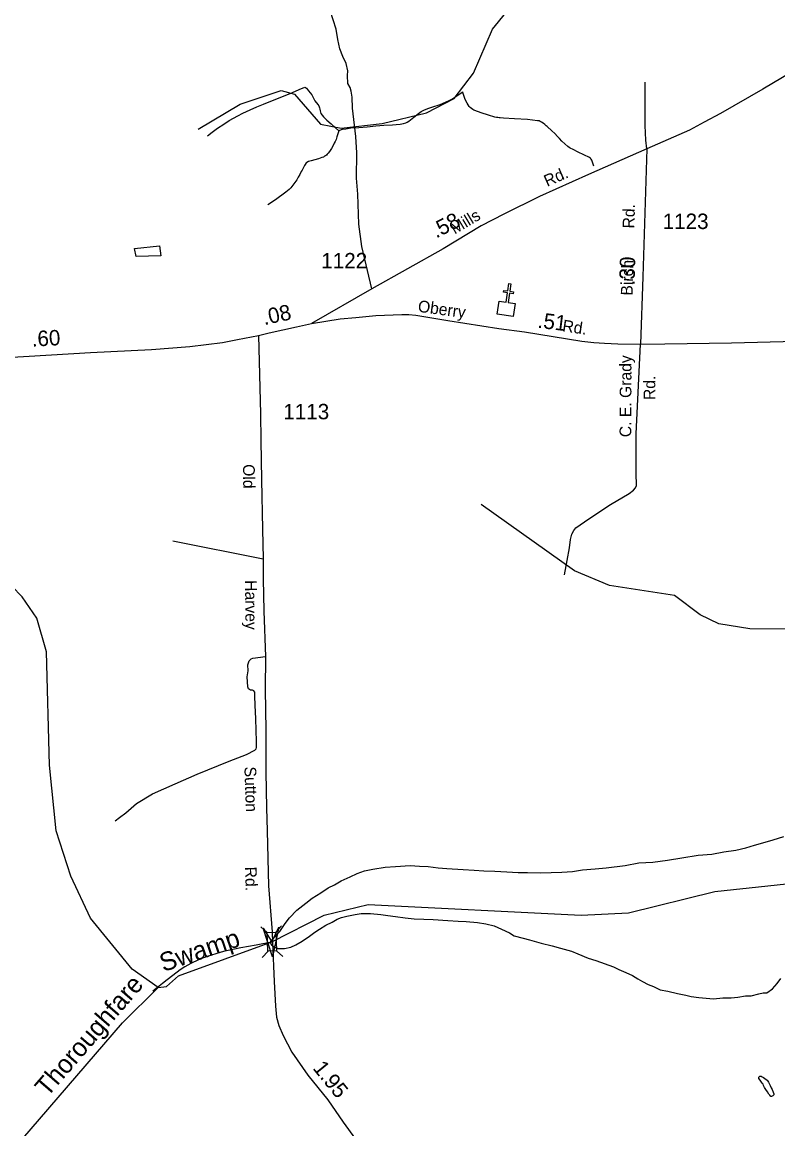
# Model space of a CAD drawing. Extents: x 2206922 to 2357709, y 510027 to 673830.
# Drawn here: x 2251460 to 2257580, y 541278 to 550239 of the extents above; entities that cross this region are included whole.
import ezdxf

# ---------------------------------------------------------------- set-up
doc = ezdxf.new("R2010")
doc.units = 0
for name, color, linetype in [('Exist Cultural Church CELL', 7, 'Continuous'), ('Exist Hydrographic Creek Single Shore', 7, 'Continuous'), ('Exist Hydrographic Creek Single Shore Label', 7, 'Continuous'), ('Exist Hydrographic Misc Water Feature', 7, 'Continuous'), ('Exist Road Non-System Type 51', 7, 'Continuous'), ('Exist Road Non-System Type 51 Label', 7, 'Continuous'), ('Exist Road Secondary Mileage Hundredths English Label', 7, 'Continuous'), ('Exist Road Secondary Structure Standard Bridge Attributed CELL', 7, 'Continuous'), ('Exist Road Secondary Structure Standard Bridge CELL', 7, 'Continuous'), ('Exist Road Secondary Type 51 Attributed', 7, 'Continuous'), ('Exist Road Secondary Type 51 Label', 7, 'Continuous'), ('Exist Road Secondary Type 51 Number Label', 7, 'Continuous')]:
    doc.layers.add(name, color=color, linetype=linetype)

msp = doc.modelspace()

# ---------------------------------------------------------------- linework, layer by layer
at = {"layer": 'Exist Cultural Church CELL'}
msp.add_lwpolyline([(2255322.1, 547979.6), (2255378.5, 547971.4), (2255389.6, 548046.7), (2255358, 548051.4), (2255360.3, 548067.2), (2255392, 548062.5), (2255400.8, 548122), (2255416.6, 548119.7), (2255407.8, 548060.2), (2255439.5, 548055.5), (2255437.1, 548039.7), (2255405.5, 548044.4), (2255394.3, 547969.1), (2255451.3, 547960.5), (2255435.7, 547855.2), (2255306.5, 547874.3)], close=True, dxfattribs=at)
at = {"layer": 'Exist Hydrographic Creek Single Shore'}
for points in [[(2252560.5, 542421.7), (2252627.5, 542430.2), (2252726.6, 542516.7), (2253480.8, 542793.8), (2253905.6, 543007.9), (2254262.6, 543095.7), (2255987.5, 543008.5), (2256370.6, 543027), (2257068.6, 543199.9), (2257851.7, 543282.5), (2258350.6, 543403.7), (2259471.6, 543820.5), (2260408.7, 544211.6)], [(2251380.6, 541104), (2252271.6, 542135.6), (2252560.5, 542421.7)]]:
    msp.add_lwpolyline(points, dxfattribs=at)
at = {"layer": 'Exist Hydrographic Misc Water Feature'}
for points in [[(2252885.5, 549371.4), (2253225.5, 549574.4), (2253557.5, 549685.8), (2253666.5, 549654.2), (2253876.5, 549413.8), (2254043.4, 549380.8), (2254376.4, 549416.8), (2254733.4, 549504.7), (2254957.6, 549621.5), (2255114.6, 549825), (2255269.4, 550182.6), (2255459.5, 550418.2)], [(2252959.5, 549316.8), (2252997.3, 549346.8), (2253043, 549379.2), (2253093, 549413.8), (2253136.5, 549442.2), (2253170.3, 549462.2), (2253206.2, 549480.7), (2253246.2, 549501.1), (2253305.7, 549529.4), (2253359.4, 549553.7), (2253413.3, 549574), (2253473.2, 549598.6), (2253562.8, 549633.4), (2253650.3, 549670), (2253704.3, 549692.3), (2253748.2, 549712.9), (2253754.1, 549710.8), (2253762.1, 549705.1), (2253778.5, 549683.2), (2253804.5, 549651.2), (2253831.2, 549601.8), (2253853.3, 549571.7), (2253861.1, 549560), (2253867.3, 549546.1), (2253871.8, 549534), (2253873.2, 549520.1), (2253879.8, 549498), (2253889.8, 549484.3), (2253900.1, 549472.2), (2253926.3, 549446.3), (2253962.2, 549416.6), (2253998.3, 549383.2), (2254024.8, 549357.3)], [(2254024.8, 549357.3), (2254033, 549363.4), (2254045.1, 549369.6), (2254054.7, 549371.4), (2254081, 549375.6), (2254120.7, 549382.2), (2254186.4, 549386.5), (2254254.4, 549391.2), (2254324.1, 549399.7), (2254390, 549404.5), (2254458.5, 549406.7), (2254488.2, 549409.1), (2254522, 549413.3), (2254548.3, 549417.5), (2254566.1, 549423.7), (2254578, 549428), (2254591.9, 549438.1), (2254605.5, 549448.2), (2254631.5, 549468.2), (2254669.3, 549498.6), (2254691, 549514.8), (2254712.9, 549526.9), (2254745.3, 549539), (2254776.7, 549551.3), (2254844.6, 549571.9), (2254886.8, 549590.3), (2254918.2, 549604.6), (2254944.2, 549618.5), (2254983.8, 549645), (2255027.7, 549675.3)], [(2256090.3, 549072.3), (2256075.9, 549114.2), (2256071.8, 549120.1), (2256067.5, 549128), (2256063.6, 549134.3), (2256061.6, 549138.2), (2256055.4, 549142), (2255963.1, 549185.1), (2255920.9, 549206.9), (2255896.9, 549218.6), (2255888.9, 549224.7), (2255878.9, 549232.7), (2255830.5, 549274), (2255810.8, 549296.1), (2255794.2, 549314), (2255772.2, 549337.6), (2255748.2, 549359.4), (2255711.7, 549392.9), (2255703.3, 549399.1), (2255691.2, 549411), (2255679.3, 549420.9), (2255665.4, 549428.7), (2255655.3, 549434.7), (2255645.3, 549438.6), (2255633.4, 549440.4), (2255551.6, 549449.9), (2255447.4, 549457.1), (2255357.2, 549462.2), (2255331.2, 549464.1), (2255321.5, 549463.9), (2255311.1, 549465.9), (2255301.2, 549467.8), (2255287.1, 549469.5), (2255271.5, 549475.5), (2255253.4, 549479.5), (2255227, 549487.1), (2255185.2, 549500.7), (2255118.7, 549526.1), (2255108.7, 549532.1), (2255099, 549540), (2255089, 549548), (2255080.8, 549555.8), (2255064.6, 549583.8), (2255048.4, 549613.4), (2255035.9, 549643.6), (2255029.5, 549669.3), (2255027.7, 549675.3)], [(2254024.8, 549357.3), (2254016.8, 549333.4), (2254009, 549309.4), (2254001.6, 549287.4), (2253995.2, 549273), (2253987.9, 549259.1), (2253977.8, 549239.1), (2253963.9, 549216.8), (2253948.1, 549190.8), (2253938.4, 549178.5), (2253930.2, 549170.8), (2253924.7, 549162.7), (2253916.5, 549156.7), (2253908.5, 549152.6), (2253900.3, 549146.6), (2253887, 549142.5), (2253860.5, 549132.3), (2253830.6, 549123.8), (2253799.2, 549115.6), (2253778.9, 549109.3), (2253764.8, 549101.3), (2253761.1, 549099.4), (2253751, 549087.1), (2253745.5, 549079.1), (2253739.3, 549062.9), (2253727.7, 549041.2), (2253719.7, 549029), (2253707.6, 549004.9), (2253696.1, 548984.7), (2253684, 548962.6), (2253666.8, 548940.5), (2253652.8, 548918.7), (2253634.6, 548898.3), (2253621.2, 548884.1), (2253595, 548862.1), (2253511.7, 548801.2), (2253449.8, 548759.1)], [(2252369.6, 548406.1), (2252571, 548428.1), (2252582, 548346.1), (2252382.1, 548340.6), (2252369.6, 548406.1)], [(2260408.7, 544211.6), (2260249.5, 544359.1), (2259996.7, 544682.3), (2259871.6, 544757), (2259620.6, 544853.9), (2259478.5, 544951.9), (2259201.5, 545216.6), (2258975.6, 545349), (2258658.5, 545404.6), (2257801.6, 545323.5), (2257351.5, 545326), (2257101.6, 545367.1), (2256950.7, 545439), (2256741.5, 545597.4), (2256215.5, 545676.9), (2255931.6, 545797.4), (2255177.6, 546334.1)], [(2252560.5, 542421.7), (2252351.5, 542570.2), (2252014.4, 542983.7), (2251854.5, 543324.7), (2251734.5, 543691.2), (2251680.6, 544223.6), (2251656.4, 545139.1), (2251578.5, 545412.9), (2251460.6, 545585.8), (2251292.5, 545759.7), (2250449.5, 546062.1), (2250157.5, 546110.6), (2249774.5, 546072.4), (2249600.6, 546013.6), (2248098.6, 545269.9)], [(2253468.3, 542786.8), (2253504.4, 542829.2), (2253546, 542877.3), (2253589.2, 542941.7), (2253624.7, 542987.9), (2253684.4, 543050.2), (2253758, 543106.8), (2253809.5, 543145.3), (2253879, 543190), (2253938.9, 543228.4), (2253988.3, 543254.6), (2254044.5, 543285.1), (2254116, 543317.7), (2254171.8, 543346.2), (2254233.5, 543366.9), (2254299.3, 543381.3), (2254399, 543395.9), (2254483.1, 543402.7), (2254603.2, 543409.7), (2254677, 543406.3), (2254748.8, 543402.7), (2254828.8, 543391.5), (2254898.9, 543386.2), (2255031, 543379.3), (2255119.1, 543373.7), (2255199.1, 543366.5), (2255287.1, 543365.4), (2255385.1, 543359.9), (2255477.4, 543355), (2255552.8, 543353.3), (2255654.5, 543352.1), (2255742.7, 543353.1), (2255830.7, 543355.6), (2255916.4, 543362.5), (2255996.8, 543374.8), (2256100.3, 543383.9), (2256188.3, 543392.5), (2256342.1, 543411.6), (2256454, 543430.8), (2256567.8, 543437.5), (2256685.5, 543452.6), (2256801.2, 543473.3), (2256933, 543494.4), (2257044.8, 543501.5), (2257142.6, 543520.4), (2257238.6, 543535.1), (2257320.4, 543553.6), (2257390.1, 543576.4), (2257475.8, 543598.7), (2257541.8, 543617.5), (2257627.3, 543644)], [(2253468.3, 542786.8), (2253478.7, 542767), (2253501.1, 542751), (2253531, 542739.2), (2253551.1, 542737.4), (2253583.1, 542737.9), (2253636.8, 542750), (2253676.6, 542768.4), (2253726.4, 542797), (2253786.3, 542837.4), (2253829.8, 542869.8), (2253867.3, 542896.2), (2253919.6, 542928.4), (2253971.3, 542952.6), (2254011, 542975), (2254046.5, 542989.1), (2254088.7, 542999.8), (2254156.2, 543014.4), (2254206.4, 543022.6), (2254280.5, 543023.2), (2254364.3, 543013.9), (2254422.2, 543006.3), (2254482.2, 542996.9), (2254560.2, 542985.5), (2254634.6, 542978.3), (2254712.3, 542976.8), (2254788.6, 542973.4), (2254908.1, 542966.3), (2254990.2, 542959.2), (2255056.2, 542957.4), (2255148.3, 542948.3), (2255214.7, 542938.8), (2255282.4, 542921.3), (2255342.8, 542893.9), (2255405, 542864.2), (2255443.1, 542840.6), (2255517.3, 542821.4), (2255569, 542807.9), (2255663.5, 542782.7), (2255751.3, 542759.3), (2255819.8, 542741.7), (2255909.6, 542716.8), (2255960.1, 542695), (2256042.1, 542659.9), (2256106.5, 542640.1), (2256248.8, 542591.4), (2256290.8, 542567.7), (2256348.8, 542544.3), (2256403.4, 542518.7), (2256445.4, 542492.9), (2256483.3, 542471.3), (2256530.1, 542447.7), (2256571.7, 542430.1), (2256626.1, 542404.4), (2256688, 542393.1), (2256766.3, 542373.5), (2256834.4, 542360.5), (2256878.3, 542350.6), (2256938.2, 542341.1), (2257000.1, 542337.5), (2257058.3, 542332), (2257134.2, 542338.8), (2257200.6, 542339.3), (2257256, 542345.5), (2257316.1, 542356.4), (2257364, 542356.4), (2257425.6, 542371.1), (2257459.8, 542379.3), (2257489.9, 542379.6), (2257535.7, 542412.1), (2257573.4, 542456.3), (2257602.9, 542494.4)], [(2253468.3, 542786.8), (2253438.3, 542780.8), (2253396.5, 542774.1), (2253354.7, 542765.8), (2253293.1, 542755.2), (2253231, 542744.7), (2253180.8, 542734.4), (2253089.3, 542713.8), (2253035.4, 542699.1), (2252983.9, 542683), (2252927.7, 542662.7), (2252888, 542648), (2252826.4, 542617.5), (2252776.6, 542591.4), (2252740.7, 542565.2), (2252681.1, 542518.6), (2252633.3, 542484), (2252597.6, 542453.8), (2252556.2, 542421.5), (2252518.3, 542393.1)], [(2257427.2, 541699.3), (2257433.6, 541703.6), (2257439.3, 541705.6), (2257443.2, 541705.4), (2257453.2, 541699.5), (2257463.3, 541693.5), (2257473.5, 541685.8), (2257483.6, 541677.8), (2257493.6, 541671.8), (2257499.6, 541664.1), (2257503.9, 541656.2), (2257509.8, 541644.3), (2257515.8, 541628.4), (2257526, 541610.2), (2257532.2, 541596.3), (2257542.4, 541574.5), (2257546.5, 541562.5), (2257546.3, 541558.5), (2257546.3, 541554.4), (2257542.4, 541548.6), (2257538.3, 541544.3), (2257534.6, 541542.4), (2257526.7, 541540.4), (2257522.3, 541540.2), (2257514.8, 541550.3), (2257506.6, 541560), (2257494.3, 541578.1), (2257482.4, 541595.7), (2257472.3, 541611.9), (2257463.7, 541629.8), (2257459.8, 541639.6), (2257451.8, 541647.7), (2257435.4, 541671.7), (2257425.4, 541685.4), (2257425.2, 541689.5), (2257425.4, 541695.5), (2257427.2, 541699.3)]]:
    msp.add_lwpolyline(points, dxfattribs=at)
at = {"layer": 'Exist Road Non-System Type 51'}
for points in [[(2254290.9, 548080.1), (2254210.5, 548422.4), (2254187.2, 548604.2), (2254177.3, 548845.4), (2254168.1, 548975.8), (2254170.4, 549179.7), (2254163.3, 549313.6), (2254135.6, 549543.3), (2254131.7, 549630.7), (2254125.4, 549680.6), (2254115, 549709.7), (2254097.8, 549742.8), (2254094.3, 549805.3), (2254098.4, 549844.7), (2254083.9, 549905), (2254056.9, 549961.1), (2254032, 550023.4), (2254015.4, 550098.2), (2254002.9, 550181.3), (2253955.2, 550333), (2253880.4, 550501.3), (2253805.6, 550927.2), (2253766.2, 551091.3)], [(2256518.7, 549212.2), (2256510.4, 549282.8), (2256503.6, 549400.7), (2256504.7, 549752.6)], [(2255850.6, 545762.6), (2255873.4, 545878.9), (2255891, 545982.5), (2255901.2, 546050.8), (2255911.3, 546093.7), (2255926.4, 546124.1), (2255944.1, 546144.3), (2256047.7, 546217.6), (2256224.5, 546333.9), (2256376.1, 546422.3), (2256411.5, 546450.2), (2256426.7, 546467.9), (2256434.2, 546488.1), (2256431.7, 546586.7), (2256431, 546905.5), (2256466.6, 547631.8)], [(2252680, 546038.8), (2252909.3, 545993.8), (2253182.3, 545938.3), (2253411.6, 545893.3)], [(2252212, 543773.1), (2252247.5, 543800.3), (2252298.3, 543837), (2252384.6, 543912.7), (2252514.6, 543990.7), (2252700.1, 544072.3), (2252877.4, 544149.2), (2253136.2, 544255.6), (2253278, 544310), (2253344.2, 544343.1), (2253356.1, 544354.9), (2253358.4, 544366.7), (2253358.4, 544416.4), (2253354.9, 544502.7), (2253351.3, 544599.7), (2253346.6, 544704.9), (2253344.2, 544783), (2253343, 544813.7), (2253337.1, 544824.4), (2253326.5, 544830.3), (2253308.8, 544831.4), (2253292.2, 544840.9), (2253286.3, 544857.5), (2253281.6, 544936.7), (2253289.9, 544987.5), (2253287.5, 545034.8), (2253299.3, 545067.9), (2253314.7, 545083.3), (2253327.7, 545089.2), (2253430.5, 545101.6)]]:
    msp.add_lwpolyline(points, dxfattribs=at)
at = {"layer": 'Exist Road Secondary Structure Standard Bridge Attributed CELL'}
msp.add_lwpolyline([(2253538, 542910.5), (2253487.1, 542672), (2253411.9, 542904), (2253480.8, 542793.8)], close=True, dxfattribs=at)
at = {"layer": 'Exist Road Secondary Structure Standard Bridge CELL'}
for p, q in [((2253559.7, 542922.8), (2253513.3, 542871.8)), ((2253391.7, 542914.9), (2253442.8, 542868.5)), ((2253451.1, 542717.6), (2253404.7, 542666.6)), ((2253520.1, 542720.9), (2253571.1, 542674.4))]:
    msp.add_line(p, q, dxfattribs=at)
msp.add_lwpolyline([(2253513.3, 542871.8), (2253520.4, 542720.9), (2253449.9, 542717.6), (2253442.8, 542868.5)], close=True, dxfattribs=at)
at = {"layer": 'Exist Road Secondary Type 51 Attributed'}
for points in [[(2259098.2, 550655.2), (2258664, 550409.9), (2257458.2, 549695.1), (2257116.3, 549498.5), (2256983.4, 549427.8), (2256864.3, 549362.7), (2256518.7, 549212.2)], [(2256518.7, 549212.2), (2256044.8, 549005.4), (2255650.3, 548828.1), (2255361.8, 548683.6), (2255176.7, 548588.2), (2254868.3, 548403.9), (2254290.9, 548080.1), (2253803.6, 547798.9)], [(2256518.7, 549212.2), (2256486.4, 548177.1), (2256466.6, 547631.8)], [(2253803.6, 547798.9), (2254035.5, 547835.3), (2254163.3, 547846.3), (2254322.7, 547862.6), (2254534.5, 547871), (2254589.9, 547872.3), (2254646.6, 547865.4), (2254908.3, 547823.9), (2255320.8, 547758.8), (2255527.5, 547731.5), (2255992.2, 547656.3), (2256090.5, 547645.2), (2256174.9, 547638.3), (2256282.9, 547634.1), (2256466.6, 547631.8)], [(2253375, 547702.5), (2253460.6, 547722.7), (2253682.1, 547770.4), (2253803.6, 547798.9)], [(2250203.2, 547439.3), (2250416.3, 547457.3), (2250821.7, 547492.8), (2251336.7, 547524), (2252012.6, 547562.9), (2252508.1, 547589), (2252817.9, 547611.6), (2253083.3, 547645.6), (2253203.1, 547668.6), (2253375, 547702.5)], [(2253375, 547702.5), (2253389.1, 547066.3), (2253393.9, 546851.1), (2253397.4, 546534.2), (2253405.3, 546133.1), (2253411.6, 545893.3), (2253412.8, 545731.3), (2253417.5, 545470), (2253430.5, 545101.6), (2253428.7, 544835.6), (2253432.3, 544507.4), (2253433.3, 544166.1), (2253437.7, 543878.3), (2253444.7, 543691.5), (2253454.8, 543246.8), (2253483.7, 542873.8), (2253487.2, 542784.2)], [(2256466.6, 547631.8), (2256663.8, 547632.8), (2257203.5, 547642.4), (2257728.2, 547656.3)], [(2253487.2, 542784.2), (2253499.6, 542471.2), (2253510.8, 542271.8), (2253519.6, 542183.8), (2253538.6, 542114.7), (2253572.3, 542033.1), (2253645, 541898.3), (2253772.6, 541712.1), (2253934, 541513.4), (2254059.8, 541332.5), (2254159.1, 541195.9)]]:
    msp.add_lwpolyline(points, dxfattribs=at)

# ---------------------------------------------------------------- texts
at = {"layer": 'Exist Hydrographic Creek Single Shore Label'}
for s, rotation, p in [('Swamp', 18.71895, (2252603.2, 542547.1)), ('Thoroughfare', 49.18462, (2251664.2, 541530.3))]:
    msp.add_text(s, height=150, rotation=rotation, dxfattribs=at).set_placement(p)
at = {"layer": 'Exist Road Non-System Type 51 Label'}
for s, p in [('C. E. Grady', (2256392.5, 546878)), ('Rd.', (2256586.9, 547178.7))]:
    msp.add_text(s, height=95, rotation=89.83193, dxfattribs=at).set_placement(p)
at = {"layer": 'Exist Road Secondary Mileage Hundredths English Label'}
for s, rotation, p in [('.58', 27.26591, (2254812.7, 548486)), ('.30', 88.47127, (2256419.1, 548106.6)), ('.08', 12.15293, (2253420.5, 547784.9)), ('.51', 352.88957, (2255629.6, 547765.4)), ('.60', 3.04205, (2251540.3, 547611.2)), ('1.95', 309.07836, (2253807.9, 541767.8))]:
    msp.add_text(s, height=125, rotation=rotation, dxfattribs=at).set_placement(p)
at = {"layer": 'Exist Road Secondary Type 51 Label'}
for s, rotation, p in [('Rd.', 23.74114, (2255710.7, 548904.5)), ('Rd.', 88.47127, (2256417.2, 548567.1)), ('Mills', 30.86281, (2254962.7, 548517.7)), ('Birch', 88.47127, (2256402.4, 548023.9)), ('Oberry', 352.23961, (2254660.5, 547894.3)), ('Rd.', 351.57707, (2255830.1, 547736.4)), ('Old', 270.43987, (2253248.3, 546659.5)), ('Harvey', 270.44866, (2253265.2, 545720.8)), ('Sutton', 272.03571, (2253259.4, 544209.7)), ('Rd.', 271.98772, (2253263.5, 543399.4))]:
    msp.add_text(s, height=95, rotation=rotation, dxfattribs=at).set_placement(p)
at = {"layer": 'Exist Road Secondary Type 51 Number Label'}
for s, p in [('1123', (2256646.5, 548563.7)), ('1122', (2253881.9, 548244.7)), ('1113', (2253574.5, 547023.1))]:
    msp.add_text(s, height=125, dxfattribs=at).set_placement(p)

doc.saveas('drawing.dxf')
